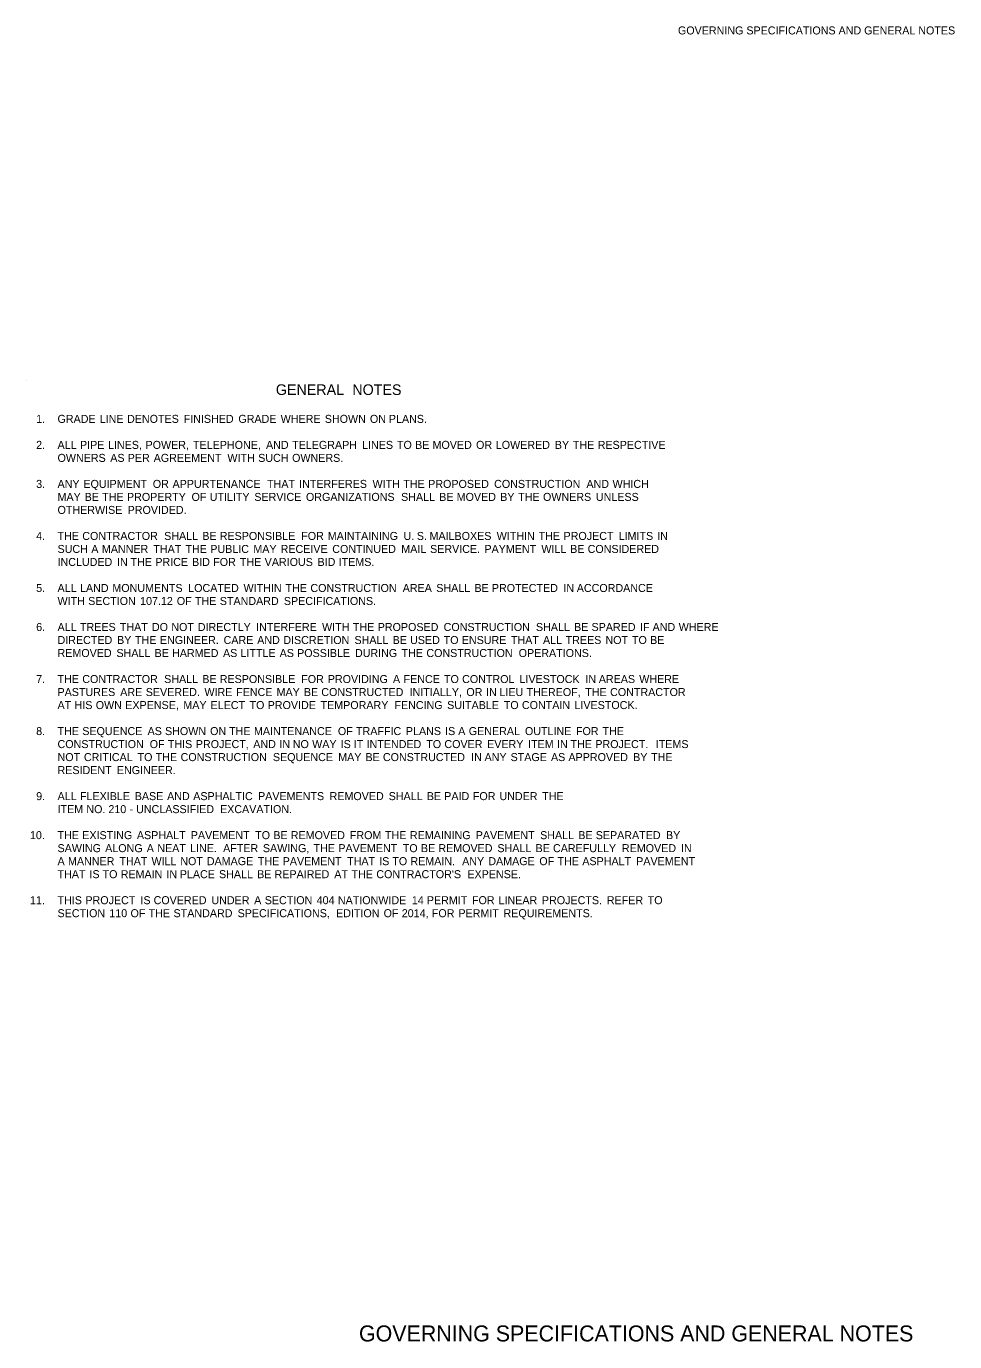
# Model space of a CAD drawing. Extents: x 2713 to 4149, y 471 to 1457.
# Drawn here: x 3453 to 4149, y 471 to 1457 of the extents above; entities that cross this region are included whole.
import ezdxf

# ---------------------------------------------------------------- set-up
doc = ezdxf.new("R2010")
doc.units = 0
for name, color, linetype in [('Default', 7, 'Continuous'), ('R_Annotation', 7, 'Continuous'), ('R_Border', 7, 'Continuous'), ('R_Logo', 7, 'Continuous')]:
    doc.layers.add(name, color=color, linetype=linetype)

msp = doc.modelspace()

# ---------------------------------------------------------------- linework, layer by layer
at = {"layer": 'R_Border'}
msp.add_line((3453.08, 1190.96), (3453.08, 1190.96), dxfattribs=at)

# ---------------------------------------------------------------- texts
at = {"layer": 'Default'}
for s, height, p in [('GENERAL', 8, (3640.11, 1180.38)), (' NOTES', 8, (3694.44, 1180.38)), ('1.', 6, (3460.47, 1159.49)), ('GRADE', 6, (3476.48, 1159.49)), (' LINE', 6, (3505.85, 1159.49)), (' DENOTES', 6, (3526.36, 1159.49)), (' FINISHED', 6, (3568.78, 1159.49)), (' GRADE', 6, (3609.79, 1159.49)), (' WHERE', 6, (3641.49, 1159.49)), (' SHOWN', 6, (3674.57, 1159.49)), (' ON', 6, (3708.35, 1159.49)), (' PLANS.', 6, (3722.57, 1159.49)), ('2.', 6, (3460.47, 1139.99)), ('ALL', 6, (3476.48, 1139.99)), (' PIPE', 6, (3491.09, 1139.99)), (' LINES,', 6, (3512.08, 1139.99)), (' POWER,', 6, (3540.22, 1139.99)), (' TELEPHONE,', 6, (3575.8, 1139.99)), (' AND', 6, (3630.5, 1139.99)), (' TELEGRAPH', 6, (3650.08, 1139.99)), (' LINES', 6, (3702.51, 1139.99)), (' TO', 6, (3728.63, 1139.99)), (' BE', 6, (3742.23, 1139.99)), (' MOVED', 6, (3755.29, 1139.99)), (' OR', 6, (3787.92, 1139.99)), (' LOWERED', 6, (3802.71, 1139.99)), (' BY', 6, (3846.98, 1139.99)), (' THE', 6, (3860.43, 1139.99)), (' RESPECTIVE', 6, (3879.08, 1139.99)), ('OWNERS', 6, (3476.48, 1130.24)), (' AS', 6, (3513.77, 1130.24)), (' PER', 6, (3526.84, 1130.24)), (' AGREEMENT', 6, (3546.3, 1130.24)), (' WITH', 6, (3601.56, 1130.24)), (' SUCH', 6, (3624.63, 1130.24)), (' OWNERS.', 6, (3650.04, 1130.24)), ('3.', 6, (3460.47, 1110.74)), ('ANY', 6, (3476.48, 1110.74)), (' EQUIPMENT', 6, (3493.65, 1110.74)), (' OR', 6, (3545.65, 1110.74)), (' APPURTENANCE', 6, (3560.44, 1110.74)), (' THAT', 6, (3631.28, 1110.74)), (' INTERFERES', 6, (3655.33, 1110.74)), (' WITH', 6, (3710.33, 1110.74)), (' THE', 6, (3733.39, 1110.74)), (' PROPOSED', 6, (3752.04, 1110.74)), (' CONSTRUCTION', 6, (3801.45, 1110.74)), (' AND', 6, (3870.62, 1110.74)), (' WHICH', 6, (3890.21, 1110.74)), ('MAY', 6, (3476.48, 1100.99)), (' BE', 6, (3494.58, 1100.99)), (' THE', 6, (3507.65, 1100.99)), (' PROPERTY', 6, (3526.3, 1100.99)), (' OF', 6, (3574.69, 1100.99)), (' UTILITY', 6, (3588.27, 1100.99)), (' SERVICE', 6, (3621.74, 1100.99)), (' ORGANIZATIONS', 6, (3660.43, 1100.99)), (' SHALL', 6, (3731.73, 1100.99)), (' BE', 6, (3760.32, 1100.99)), (' MOVED', 6, (3773.39, 1100.99)), (' BY', 6, (3806.01, 1100.99)), (' THE', 6, (3819.46, 1100.99)), (' OWNERS', 6, (3838.11, 1100.99)), (' UNLESS', 6, (3877.73, 1100.99)), ('OTHERWISE', 6, (3476.48, 1091.24)), (' PROVIDED.', 6, (3526.8, 1091.24)), ('4.', 6, (3460.47, 1071.74)), ('THE', 6, (3476.48, 1071.74)), (' CONTRACTOR', 6, (3492.8, 1071.74)), (' SHALL', 6, (3554.17, 1071.74)), (' BE', 6, (3582.76, 1071.74)), (' RESPONSIBLE', 6, (3595.82, 1071.74)), (' FOR', 6, (3656.88, 1071.74)), (' MAINTAINING', 6, (3676.79, 1071.74)), (' U.', 6, (3733.55, 1071.74)), (' S.', 6, (3743.53, 1071.74)), (' MAILBOXES', 6, (3753.05, 1071.74)), (' WITHIN', 6, (3803.39, 1071.74)), (' THE', 6, (3834.83, 1071.74)), (' PROJECT', 6, (3853.48, 1071.74)), (' LIMITS', 6, (3894.78, 1071.74)), (' IN', 6, (3923.68, 1071.74)), ('SUCH', 6, (3476.48, 1061.99)), (' A', 6, (3499.56, 1061.99)), (' MANNER', 6, (3507.49, 1061.99)), (' THAT', 6, (3546.04, 1061.99)), (' THE', 6, (3570.09, 1061.99)), (' PUBLIC', 6, (3588.74, 1061.99)), (' MAY', 6, (3621.02, 1061.99)), (' RECEIVE', 6, (3641.45, 1061.99)), (' CONTINUED', 6, (3680.14, 1061.99)), (' MAIL', 6, (3731.86, 1061.99)), (' SERVICE.', 6, (3753.45, 1061.99)), (' PAYMENT', 6, (3794.18, 1061.99)), (' WILL', 6, (3836.87, 1061.99)), (' BE', 6, (3858.46, 1061.99)), (' CONSIDERED', 6, (3871.53, 1061.99)), ('INCLUDED', 6, (3476.48, 1052.24)), (' IN', 6, (3518.88, 1052.24)), (' THE', 6, (3528.91, 1052.24)), (' PRICE', 6, (3547.56, 1052.24)), (' BID', 6, (3575.06, 1052.24)), (' FOR', 6, (3590.92, 1052.24)), (' THE', 6, (3610.83, 1052.24)), (' VARIOUS', 6, (3629.48, 1052.24)), (' BID', 6, (3669.1, 1052.24)), (' ITEMS.', 6, (3684.96, 1052.24)), ('5.', 6, (3460.47, 1032.74)), ('ALL', 6, (3476.48, 1032.74)), (' LAND', 6, (3491.09, 1032.74)), (' MONUMENTS', 6, (3515.33, 1032.74)), (' LOCATED', 6, (3572.18, 1032.74)), (' WITHIN', 6, (3613.66, 1032.74)), (' THE', 6, (3645.1, 1032.74)), (' CONSTRUCTION', 6, (3663.75, 1032.74)), (' AREA', 6, (3732.93, 1032.74)), (' SHALL', 6, (3758.11, 1032.74)), (' BE', 6, (3786.7, 1032.74)), (' PROTECTED', 6, (3799.76, 1032.74)), (' IN', 6, (3853.35, 1032.74)), (' ACCORDANCE', 6, (3863.38, 1032.74)), ('WITH', 6, (3476.48, 1022.99)), (' SECTION', 6, (3497.22, 1022.99)), (' 107.12', 6, (3536.12, 1022.99)), (' OF', 6, (3563.64, 1022.99)), (' THE', 6, (3577.22, 1022.99)), (' STANDARD', 6, (3595.87, 1022.99)), (' SPECIFICATIONS.', 6, (3643.87, 1022.99)), ('6.', 6, (3460.47, 1003.49)), ('ALL', 6, (3476.48, 1003.49)), (' TREES', 6, (3491.09, 1003.49)), (' THAT', 6, (3520.94, 1003.49)), (' DO', 6, (3544.99, 1003.49)), (' NOT', 6, (3559.52, 1003.49)), (' DIRECTLY', 6, (3579.37, 1003.49)), (' INTERFERE', 6, (3623.1, 1003.49)), (' WITH', 6, (3672.49, 1003.49)), (' THE', 6, (3695.56, 1003.49)), (' PROPOSED', 6, (3714.21, 1003.49)), (' CONSTRUCTION', 6, (3763.61, 1003.49)), (' SHALL', 6, (3832.79, 1003.49)), (' BE', 6, (3861.38, 1003.49)), (' SPARED', 6, (3874.45, 1003.49)), (' IF', 6, (3910.81, 1003.49)), (' AND', 6, (3920.2, 1003.49)), (' WHERE', 6, (3939.78, 1003.49)), ('DIRECTED', 6, (3476.48, 993.74)), (' BY', 6, (3518.88, 993.74)), (' THE', 6, (3532.33, 993.74)), (' ENGINEER.', 6, (3550.98, 993.74)), (' CARE', 6, (3598.7, 993.74)), (' AND', 6, (3623.87, 993.74)), (' DISCRETION', 6, (3643.46, 993.74)), (' SHALL', 6, (3696.8, 993.74)), (' BE', 6, (3725.39, 993.74)), (' USED', 6, (3738.46, 993.74)), (' TO', 6, (3763.64, 993.74)), (' ENSURE', 6, (3777.23, 993.74)), (' THAT', 6, (3814.05, 993.74)), (' ALL', 6, (3838.1, 993.74)), (' TREES', 6, (3855.05, 993.74)), (' NOT', 6, (3884.89, 993.74)), (' TO', 6, (3904.75, 993.74)), (' BE', 6, (3918.35, 993.74)), ('REMOVED', 6, (3476.48, 983.99)), (' SHALL', 6, (3518.42, 983.99)), (' BE', 6, (3547.01, 983.99)), (' HARMED', 6, (3560.08, 983.99)), (' AS', 6, (3598.29, 983.99)), (' LITTLE', 6, (3611.37, 983.99)), (' AS', 6, (3640.73, 983.99)), (' POSSIBLE', 6, (3653.81, 983.99)), (' DURING', 6, (3697.16, 983.99)), (' THE', 6, (3732.03, 983.99)), (' CONSTRUCTION', 6, (3750.68, 983.99)), (' OPERATIONS.', 6, (3819.86, 983.99)), ('7.', 6, (3460.47, 964.49)), ('THE', 6, (3476.48, 964.49)), (' CONTRACTOR', 6, (3492.8, 964.49)), (' SHALL', 6, (3554.17, 964.49)), (' BE', 6, (3582.76, 964.49)), (' RESPONSIBLE', 6, (3595.82, 964.49)), (' FOR', 6, (3656.88, 964.49)), (' PROVIDING', 6, (3676.79, 964.49)), (' A', 6, (3725.64, 964.49)), (' FENCE', 6, (3733.58, 964.49)), (' TO', 6, (3763.87, 964.49)), (' CONTROL', 6, (3777.47, 964.49)), (' LIVESTOCK', 6, (3820.49, 964.49)), (' IN', 6, (3869.86, 964.49)), (' AREAS', 6, (3879.88, 964.49)), (' WHERE', 6, (3910.2, 964.49)), ('PASTURES', 6, (3476.48, 954.74)), (' ARE', 6, (3521.23, 954.74)), (' SEVERED.', 6, (3540.35, 954.74)), (' WIRE', 6, (3584.35, 954.74)), (' FENCE', 6, (3608.12, 954.74)), (' MAY', 6, (3638.42, 954.74)), (' BE', 6, (3658.85, 954.74)), (' CONSTRUCTED', 6, (3671.92, 954.74)), (' INITIALLY,', 6, (3738.08, 954.74)), (' OR', 6, (3780.65, 954.74)), (' IN', 6, (3795.44, 954.74)), (' LIEU', 6, (3805.47, 954.74)), (' THEREOF,', 6, (3825.75, 954.74)), (' THE', 6, (3869.72, 954.74)), (' CONTRACTOR', 6, (3888.37, 954.74)), ('AT', 6, (3476.48, 944.99)), (' HIS', 6, (3487.02, 944.99)), (' OWN', 6, (3502.89, 944.99)), (' EXPENSE,', 6, (3525.02, 944.99)), (' MAY', 6, (3568.54, 944.99)), (' ELECT', 6, (3588.97, 944.99)), (' TO', 6, (3618.15, 944.99)), (' PROVIDE', 6, (3631.75, 944.99)), (' TEMPORARY', 6, (3671.37, 944.99)), (' FENCING', 6, (3726.74, 944.99)), (' SUITABLE', 6, (3766.27, 944.99)), (' TO', 6, (3808.69, 944.99)), (' CONTAIN', 6, (3822.28, 944.99)), (' LIVESTOCK.', 6, (3861.65, 944.99)), ('8.', 6, (3460.47, 925.49)), ('THE', 6, (3476.48, 925.49)), (' SEQUENCE', 6, (3492.8, 925.49)), (' AS', 6, (3541.74, 925.49)), (' SHOWN', 6, (3554.81, 925.49)), (' ON', 6, (3588.59, 925.49)), (' THE', 6, (3602.81, 925.49)), (' MAINTENANCE', 6, (3621.46, 925.49)), (' OF', 6, (3684.36, 925.49)), (' TRAFFIC', 6, (3697.95, 925.49)), (' PLANS', 6, (3735.34, 925.49)), (' IS', 6, (3764.72, 925.49)), (' A', 6, (3774.53, 925.49)), (' GENERAL', 6, (3782.46, 925.49)), (' OUTLINE', 6, (3824.56, 925.49)), (' FOR', 6, (3862.78, 925.49)), (' THE', 6, (3882.69, 925.49)), ('CONSTRUCTION', 6, (3476.48, 915.74)), (' OF', 6, (3543.33, 915.74)), (' THIS', 6, (3556.91, 915.74)), (' PROJECT,', 6, (3577.9, 915.74)), (' AND', 6, (3620.94, 915.74)), (' IN', 6, (3640.53, 915.74)), (' NO', 6, (3650.55, 915.74)), (' WAY', 6, (3665.08, 915.74)), (' IS', 6, (3686.44, 915.74)), (' IT', 6, (3696.25, 915.74)), (' INTENDED', 6, (3705.86, 915.74)), (' TO', 6, (3750.59, 915.74)), (' COVER', 6, (3764.19, 915.74)), (' EVERY', 6, (3796.22, 915.74)), (' ITEM', 6, (3826.91, 915.74)), (' IN', 6, (3848.63, 915.74)), (' THE', 6, (3858.66, 915.74)), (' PROJECT.', 6, (3877.31, 915.74)), ('  ITEMS', 6, (3920.36, 915.74)), ('NOT', 6, (3476.48, 905.99)), (' CRITICAL', 6, (3494.01, 905.99)), (' TO', 6, (3534.23, 905.99)), (' THE', 6, (3547.83, 905.99)), (' CONSTRUCTION', 6, (3566.48, 905.99)), (' SEQUENCE', 6, (3635.65, 905.99)), (' MAY', 6, (3684.59, 905.99)), (' BE', 6, (3705.03, 905.99)), (' CONSTRUCTED', 6, (3718.09, 905.99)), (' IN', 6, (3784.25, 905.99)), (' ANY', 6, (3794.28, 905.99)), (' STAGE', 6, (3813.78, 905.99)), (' AS', 6, (3844.08, 905.99)), (' APPROVED', 6, (3857.16, 905.99)), (' BY', 6, (3905.63, 905.99)), (' THE', 6, (3919.08, 905.99)), ('RESIDENT', 6, (3476.48, 896.24)), (' ENGINEER.', 6, (3518.7, 896.24)), ('9.', 6, (3460.47, 876.74)), ('ALL', 6, (3476.48, 876.74)), (' FLEXIBLE', 6, (3491.09, 876.74)), (' BASE', 6, (3532.11, 876.74)), (' AND', 6, (3556.37, 876.74)), (' ASPHALTIC', 6, (3575.95, 876.74)), (' PAVEMENTS', 6, (3624.53, 876.74)), (' REMOVED', 6, (3678.14, 876.74)), (' SHALL', 6, (3722.41, 876.74)), (' BE', 6, (3751, 876.74)), (' PAID', 6, (3764.07, 876.74)), (' FOR', 6, (3785.52, 876.74)), (' UNDER', 6, (3805.43, 876.74)), (' THE', 6, (3837.46, 876.74)), ('ITEM', 6, (3476.48, 866.99)), (' NO.', 6, (3495.87, 866.99)), (' 210', 6, (3512.37, 866.99)), (' -', 6, (3528.28, 866.99)), (' UNCLASSIFIED', 6, (3533.13, 866.99)), (' EXCAVATION.', 6, (3596.04, 866.99)), ('10.', 6, (3455.81, 847.49)), ('THE', 6, (3476.48, 847.49)), (' EXISTING', 6, (3492.8, 847.49)), (' ASPHALT', 6, (3533.73, 847.49)), (' PAVEMENT', 6, (3574.1, 847.49)), (' TO', 6, (3622.38, 847.49)), (' BE', 6, (3635.98, 847.49)), (' REMOVED', 6, (3649.05, 847.49)), (' FROM', 6, (3693.32, 847.49)), (' THE', 6, (3719.7, 847.49)), (' REMAINING', 6, (3738.35, 847.49)), (' PAVEMENT', 6, (3787.66, 847.49)), (' SHALL', 6, (3835.94, 847.49)), (' BE', 6, (3864.53, 847.49)), (' SEPARATED', 6, (3877.6, 847.49)), (' BY', 6, (3930.27, 847.49)), ('SAWING', 6, (3476.48, 837.74)), (' ALONG', 6, (3509.95, 837.74)), (' A', 6, (3541.1, 837.74)), (' NEAT', 6, (3549.04, 837.74)), (' LINE.', 6, (3573.56, 837.74)), ('  AFTER', 6, (3596.12, 837.74)), (' SAWING,', 6, (3628.15, 837.74)), (' THE', 6, (3666.06, 837.74)), (' PAVEMENT', 6, (3684.71, 837.74)), (' TO', 6, (3732.99, 837.74)), (' BE', 6, (3746.59, 837.74)), (' REMOVED', 6, (3759.65, 837.74)), (' SHALL', 6, (3803.92, 837.74)), (' BE', 6, (3832.52, 837.74)), (' CAREFULLY', 6, (3845.58, 837.74)), (' REMOVED', 6, (3897.23, 837.74)), (' IN', 6, (3941.5, 837.74)), ('A', 6, (3476.48, 827.99)), (' MANNER', 6, (3482.08, 827.99)), (' THAT', 6, (3520.63, 827.99)), (' WILL', 6, (3544.68, 827.99)), (' NOT', 6, (3566.27, 827.99)), (' DAMAGE', 6, (3586.13, 827.99)), (' THE', 6, (3624.35, 827.99)), (' PAVEMENT', 6, (3642.99, 827.99)), (' THAT', 6, (3691.28, 827.99)), (' IS', 6, (3715.33, 827.99)), (' TO', 6, (3725.14, 827.99)), (' REMAIN.', 6, (3738.73, 827.99)), ('  ANY', 6, (3775.26, 827.99)), (' DAMAGE', 6, (3797.1, 827.99)), (' OF', 6, (3835.31, 827.99)), (' THE', 6, (3848.9, 827.99)), (' ASPHALT', 6, (3867.55, 827.99)), (' PAVEMENT', 6, (3907.92, 827.99)), ('THAT', 6, (3476.48, 818.24)), (' IS', 6, (3498.2, 818.24)), (' TO', 6, (3508.01, 818.24)), (' REMAIN', 6, (3521.6, 818.24)), (' IN', 6, (3555.85, 818.24)), (' PLACE', 6, (3565.88, 818.24)), (' SHALL', 6, (3595.25, 818.24)), (' BE', 6, (3623.84, 818.24)), (' REPAIRED', 6, (3636.91, 818.24)), (' AT', 6, (3681.65, 818.24)), (' THE', 6, (3694.53, 818.24)), (" CONTRACTOR'S", 6, (3713.17, 818.24)), (' EXPENSE.', 6, (3781.41, 818.24)), ('11.', 6, (3455.81, 798.74)), ('THIS', 6, (3476.48, 798.74)), (' PROJECT', 6, (3495.14, 798.74)), (' IS', 6, (3536.43, 798.74)), (' COVERED', 6, (3546.24, 798.74)), (' UNDER', 6, (3589.58, 798.74)), (' A', 6, (3621.61, 798.74)), (' SECTION', 6, (3629.54, 798.74)), (' 404', 6, (3668.45, 798.74)), (' NATIONWIDE', 6, (3684.35, 798.74)), (' 14', 6, (3739.79, 798.74)), (' PERMIT', 6, (3751.03, 798.74)), (' FOR', 6, (3784.86, 798.74)), (' LINEAR', 6, (3804.78, 798.74)), (' PROJECTS.', 6, (3837.27, 798.74)), (' REFER', 6, (3885.92, 798.74)), (' TO', 6, (3916.55, 798.74)), ('SECTION', 6, (3476.48, 788.99)), (' 110', 6, (3513.06, 788.99)), (' OF', 6, (3528.96, 788.99)), (' THE', 6, (3542.55, 788.99)), (' STANDARD', 6, (3561.2, 788.99)), (' SPECIFICATIONS,', 6, (3609.2, 788.99)), (' EDITION', 6, (3682.99, 788.99)), (' OF', 6, (3718.63, 788.99)), (' 2014,', 6, (3732.22, 788.99)), (' FOR', 6, (3754.77, 788.99)), (' PERMIT', 6, (3774.68, 788.99)), (' REQUIREMENTS.', 6, (3808.51, 788.99))]:
    msp.add_text(s, height=height, dxfattribs=at).set_placement(p)
at = {"layer": 'R_Annotation'}
msp.add_text('GOVERNING SPECIFICATIONS AND GENERAL NOTES', height=12, dxfattribs=at).set_placement((3702.38, 471.01))
at = {"layer": 'R_Logo'}
msp.add_text('GOVERNING SPECIFICATIONS AND GENERAL NOTES', height=6, dxfattribs=at).set_placement((3941.46, 1450.62))

doc.saveas('drawing.dxf')
